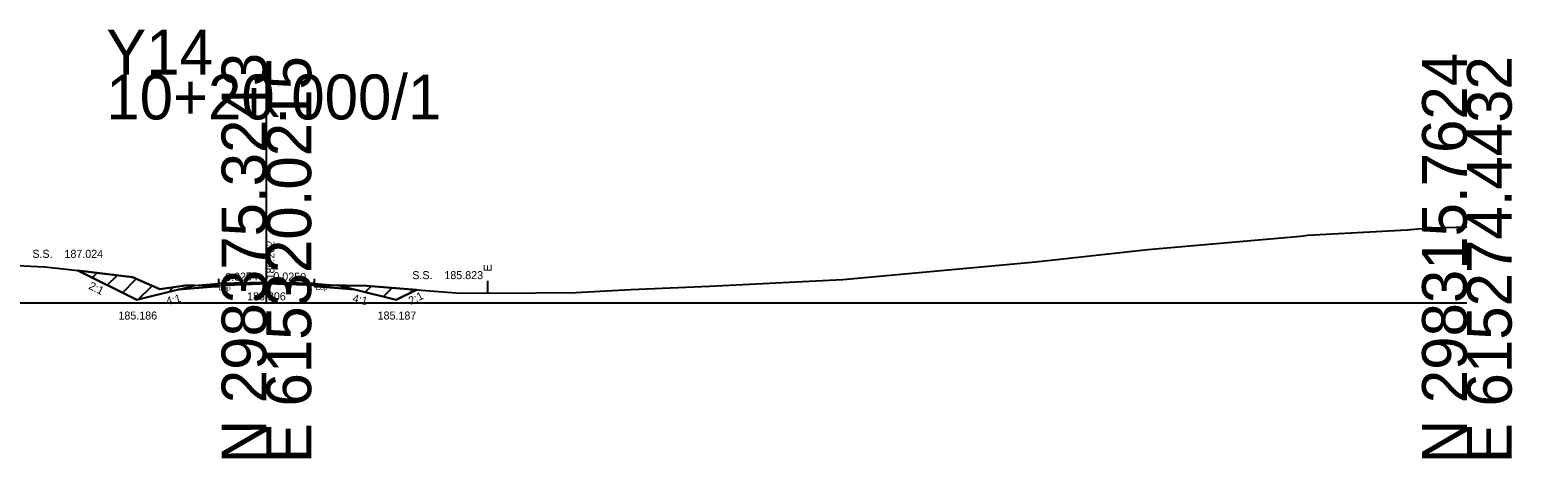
# Model space of a CAD drawing. Extents: x 517327 to 517505, y 114839 to 117370.
# Drawn here: x 517412.6 to 517505.2, y 115338.7 to 115365.4 of the extents above; entities that cross this region are included whole.
import ezdxf

# ---------------------------------------------------------------- set-up
doc = ezdxf.new("R2010")
doc.units = 0
for name, color, linetype in [('Exist XS Ground Line', 7, 'Continuous'), ('Old_Level_60', 7, 'Continuous'), ('Old_Level_63', 7, 'Continuous'), ('Prop XS Dump Level', 7, 'Continuous'), ('Prop XS Earthwork Shape', 7, 'Continuous'), ('Prop XS Elevation Labels', 7, 'Continuous'), ('Prop XS EOT Tick Mark', 7, 'Continuous'), ('Prop XS Exc Vertical Line 1', 7, 'Continuous'), ('Prop XS Finish Grade', 7, 'Continuous'), ('Prop XS Finish Grade Earthwork', 7, 'Continuous'), ('Prop XS Finish Grade Pavement', 7, 'Continuous'), ('Prop XS Hydro Elevations', 7, 'Continuous'), ('Prop XS Label Text', 7, 'Continuous'), ('Prop XS Pvmt Edge Slope', 7, 'Continuous'), ('Prop XS SE Text', 7, 'Continuous'), ('Prop XS Side Slope Text', 7, 'Continuous'), ('Prop XS Subgrade Earthwork', 7, 'Continuous'), ('Prop XS Suitable Common Exc Shape', 7, 'Continuous'), ('Scratch_Level_0', 7, 'Continuous')]:
    doc.layers.add(name, color=color, linetype=linetype)

msp = doc.modelspace()

# ---------------------------------------------------------------- linework, layer by layer
at = {"layer": 'Exist XS Ground Line'}
for p, q in [((517492.401, 115352.596), (517498.643, 115352.931)), ((517498.643, 115352.931), (517499.793, 115353.024)), ((517499.793, 115353.024), (517502.365, 115353.116)), ((517482.436, 115351.7), (517491.961, 115352.543)), ((517491.961, 115352.543), (517492.401, 115352.596)), ((517475.406, 115350.941), (517482.436, 115351.7)), ((517409.541, 115350.799), (517413.527, 115350.62)), ((517413.527, 115350.62), (517415.036, 115350.456)), ((517415.036, 115350.456), (517418.99, 115349.974)), ((517463.378, 115349.826), (517475.406, 115350.941)), ((517418.99, 115349.974), (517420.697, 115349.223)), ((517420.697, 115349.223), (517422.46, 115349.469)), ((517422.46, 115349.469), (517423.982, 115349.463)), ((517423.982, 115349.463), (517424.392, 115349.457)), ((517424.392, 115349.457), (517424.863, 115349.474)), ((517424.863, 115349.474), (517427.48, 115349.575)), ((517427.48, 115349.575), (517428.001, 115349.557)), ((517428.001, 115349.557), (517430.443, 115349.473)), ((517430.443, 115349.473), (517431.026, 115349.479)), ((517431.026, 115349.479), (517433.64, 115349.429)), ((517433.64, 115349.429), (517438.11, 115349.08)), ((517446.704, 115349.019), (517450.132, 115349.202)), ((517450.132, 115349.202), (517455.04, 115349.422)), ((517455.04, 115349.422), (517462.94, 115349.802)), ((517462.94, 115349.802), (517463.378, 115349.826)), ((517438.11, 115349.08), (517439.215, 115348.988)), ((517439.215, 115348.988), (517441.688, 115348.985)), ((517441.688, 115348.985), (517446.704, 115349.019))]:
    msp.add_line(p, q, dxfattribs=at)
at = {"layer": 'Old_Level_63'}
for p, q in [((517427.365, 115348.365), (517427.365, 115362.618)), ((517352.365, 115348.365), (517427.365, 115348.365)), ((517427.365, 115348.365), (517502.365, 115348.365))]:
    msp.add_line(p, q, dxfattribs=at)
at = {"layer": 'Prop XS Dump Level'}
for p, q in [((517424.365, 115349.571), (517427.365, 115349.647)), ((517427.365, 115349.647), (517430.365, 115349.572))]:
    msp.add_line(p, q, dxfattribs=at)
at = {"layer": 'Prop XS Earthwork Shape'}
for points in [[(517415.588, 115350.389), (517418.99, 115349.974), (517420.697, 115349.223), (517422.46, 115349.469), (517423.982, 115349.463), (517424.393, 115349.457), (517424.365, 115349.391), (517424.18, 115349.386), (517422.865, 115349.281), (517421.865, 115349.201), (517419.265, 115348.551)], [(517430.363, 115349.476), (517430.443, 115349.473), (517431.026, 115349.479), (517433.64, 115349.429), (517436.736, 115349.187), (517435.465, 115348.552), (517432.864, 115349.202), (517431.865, 115349.282), (517430.55, 115349.387), (517430.365, 115349.392)]]:
    msp.add_lwpolyline(points, close=True, dxfattribs=at)
at = {"layer": 'Prop XS EOT Tick Mark'}
for p, q in [((517424.365, 115349.875), (517424.365, 115349.571)), ((517430.365, 115349.572), (517430.365, 115349.876))]:
    msp.add_line(p, q, dxfattribs=at)
at = {"layer": 'Prop XS Exc Vertical Line 1'}
msp.add_line((517441.185, 115349.736), (517441.185, 115348.986), dxfattribs=at)
at = {"layer": 'Prop XS Finish Grade'}
for p, q in [((517421.865, 115349.201), (517422.865, 115349.451)), ((517422.865, 115349.451), (517424.365, 115349.571)), ((517430.365, 115349.572), (517431.865, 115349.452)), ((517431.865, 115349.452), (517432.864, 115349.202))]:
    msp.add_line(p, q, dxfattribs=at)
at = {"layer": 'Prop XS Finish Grade Earthwork'}
for p, q in [((517415.588, 115350.389), (517419.265, 115348.551)), ((517419.265, 115348.551), (517421.865, 115349.201)), ((517432.864, 115349.202), (517435.465, 115348.552)), ((517435.465, 115348.552), (517436.737, 115349.188))]:
    msp.add_line(p, q, dxfattribs=at)
at = {"layer": 'Prop XS Finish Grade Pavement'}
for p, q in [((517427.365, 115349.647), (517424.365, 115349.571)), ((517430.365, 115349.572), (517427.365, 115349.647))]:
    msp.add_line(p, q, dxfattribs=at)
at = {"layer": 'Prop XS Pvmt Edge Slope'}
for p, q in [((517424.18, 115349.386), (517424.365, 115349.571)), ((517430.365, 115349.572), (517430.55, 115349.387))]:
    msp.add_line(p, q, dxfattribs=at)
at = {"layer": 'Prop XS Subgrade Earthwork'}
for p, q in [((517421.865, 115349.201), (517422.865, 115349.281)), ((517422.865, 115349.281), (517424.18, 115349.386)), ((517424.18, 115349.386), (517424.365, 115349.391)), ((517424.365, 115349.391), (517424.391, 115349.391)), ((517424.393, 115349.457), (517424.391, 115349.391)), ((517430.365, 115349.392), (517430.363, 115349.476)), ((517430.365, 115349.392), (517430.55, 115349.387)), ((517430.55, 115349.387), (517431.865, 115349.282)), ((517431.865, 115349.282), (517432.864, 115349.202))]:
    msp.add_line(p, q, dxfattribs=at)
at = {"layer": 'Prop XS Suitable Common Exc Shape'}
for points in [[(517423.982, 115349.463), (517424.392, 115349.457), (517424.365, 115349.391), (517424.18, 115349.386), (517422.865, 115349.281), (517421.865, 115349.201), (517419.265, 115348.551), (517415.588, 115350.389), (517418.99, 115349.974), (517420.697, 115349.223), (517422.46, 115349.469)], [(517435.465, 115348.552), (517436.737, 115349.188), (517433.64, 115349.429), (517431.026, 115349.479), (517430.443, 115349.473), (517430.363, 115349.476), (517430.365, 115349.392), (517430.55, 115349.387), (517431.865, 115349.282), (517432.864, 115349.202)]]:
    msp.add_lwpolyline(points, close=True, dxfattribs=at)
at = {"layer": 'Scratch_Level_0'}
for p, q in [((517416.484, 115349.941), (517416.785, 115350.243)), ((517417.426, 115349.47), (517418.046, 115350.089)), ((517418.369, 115348.998), (517419.236, 115349.866)), ((517419.359, 115348.574), (517420.218, 115349.433)), ((517421.245, 115349.046), (517421.54, 115349.341)), ((517432.398, 115349.318), (517432.533, 115349.453)), ((517433.53, 115349.035), (517433.903, 115349.409)), ((517434.661, 115348.753), (517435.215, 115349.306)), ((517436.284, 115348.961), (517436.527, 115349.204))]:
    msp.add_line(p, q, dxfattribs=at)
for points in [[(517415.588, 115350.389), (517419.265, 115348.551), (517421.865, 115349.201), (517422.884, 115349.455), (517422.46, 115349.469), (517420.697, 115349.223), (517418.99, 115349.974)], [(517436.737, 115349.188), (517435.465, 115348.552), (517432.864, 115349.202), (517431.8, 115349.468), (517433.64, 115349.429)]]:
    msp.add_lwpolyline(points, close=True, dxfattribs=at)

# ---------------------------------------------------------------- texts
at = {"layer": 'Old_Level_60'}
msp.add_text('186.206', height=0.5, dxfattribs=at).set_placement((517426.159, 115348.529))
at = {"layer": 'Old_Level_63'}
for s, p in [('Y14', (517417.362, 115362.618)), ('10+20.000/1', (517417.365, 115359.818))]:
    msp.add_text(s, height=2.8, dxfattribs=at).set_placement(p)
for s, p in [('N 298375.3243', (517427.365, 115338.364)), ('E 615320.0215', (517430.165, 115338.365)), ('N 298315.7624', (517502.365, 115338.365)), ('E 615274.4432', (517505.165, 115338.365))]:
    msp.add_text(s, height=2.8, rotation=90, dxfattribs=at).set_placement(p)
at = {"layer": 'Prop XS Dump Level'}
for s, height, p in [('Case1', 0.0122, (517422.865, 115349.438)), ('Eop', 0.3, (517424.391, 115349.157)), ('Eop', 0.3, (517430.444, 115349.173)), ('Case1', 0.0122, (517431.865, 115349.439))]:
    msp.add_text(s, height=height, dxfattribs=at).set_placement(p)
at = {"layer": 'Prop XS Elevation Labels'}
msp.add_text(' 186.282', height=0.5, rotation=90, dxfattribs=at).set_placement((517427.865, 115349.647))
at = {"layer": 'Prop XS Exc Vertical Line 1'}
msp.add_text('E', height=0.5, rotation=90, dxfattribs=at).set_placement((517441.435, 115350.328))
at = {"layer": 'Prop XS Hydro Elevations'}
for s, p in [('S.S.    187.024', (517412.741, 115351.18)), ('S.S.    185.823', (517436.477, 115349.852))]:
    msp.add_text(s, height=0.5, dxfattribs=at).set_placement(p)
at = {"layer": 'Prop XS Label Text'}
for rotation, p in [(14.03624, (517421.164, 115348.219)), (345.96376, (517432.709, 115348.445))]:
    msp.add_text('4:1', height=0.5, rotation=rotation, dxfattribs=at).set_placement(p)
at = {"layer": 'Prop XS SE Text'}
for s, rotation, p in [('0.0254', 1.45499, (517424.796, 115349.734)), ('0.0250', 358.5656, (517427.793, 115349.788))]:
    msp.add_text(s, height=0.5, rotation=rotation, dxfattribs=at).set_placement(p)
at = {"layer": 'Prop XS Side Slope Text'}
for rotation, p in [(333.43495, (517416.219, 115349.272)), (26.56505, (517436.396, 115348.237))]:
    msp.add_text('2:1', height=0.5, rotation=rotation, dxfattribs=at).set_placement(p)
for s, p in [('185.186', (517418.119, 115347.331)), ('185.187', (517434.312, 115347.332))]:
    msp.add_text(s, height=0.5, dxfattribs=at).set_placement(p)

doc.saveas('drawing.dxf')
